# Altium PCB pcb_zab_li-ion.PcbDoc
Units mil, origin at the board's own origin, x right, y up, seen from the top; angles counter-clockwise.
Board outline 1000 x 550 mil, 2 copper layers (Top Layer, Bottom Layer); 14 components, 7 nets, 29 pads, 0 vias.
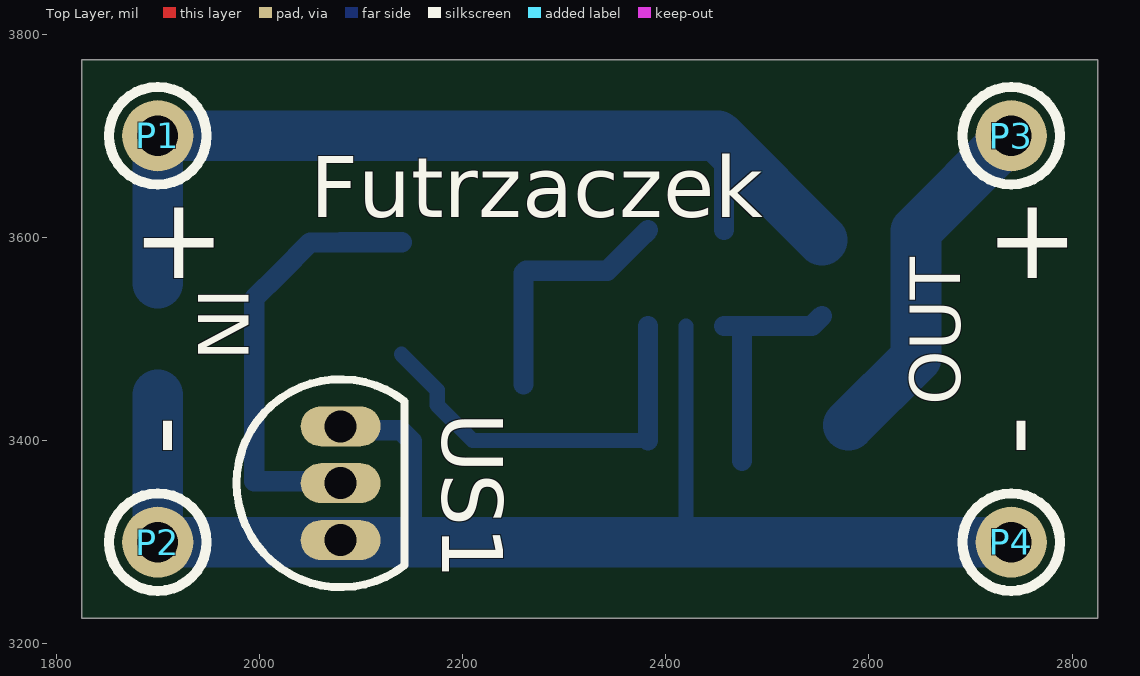
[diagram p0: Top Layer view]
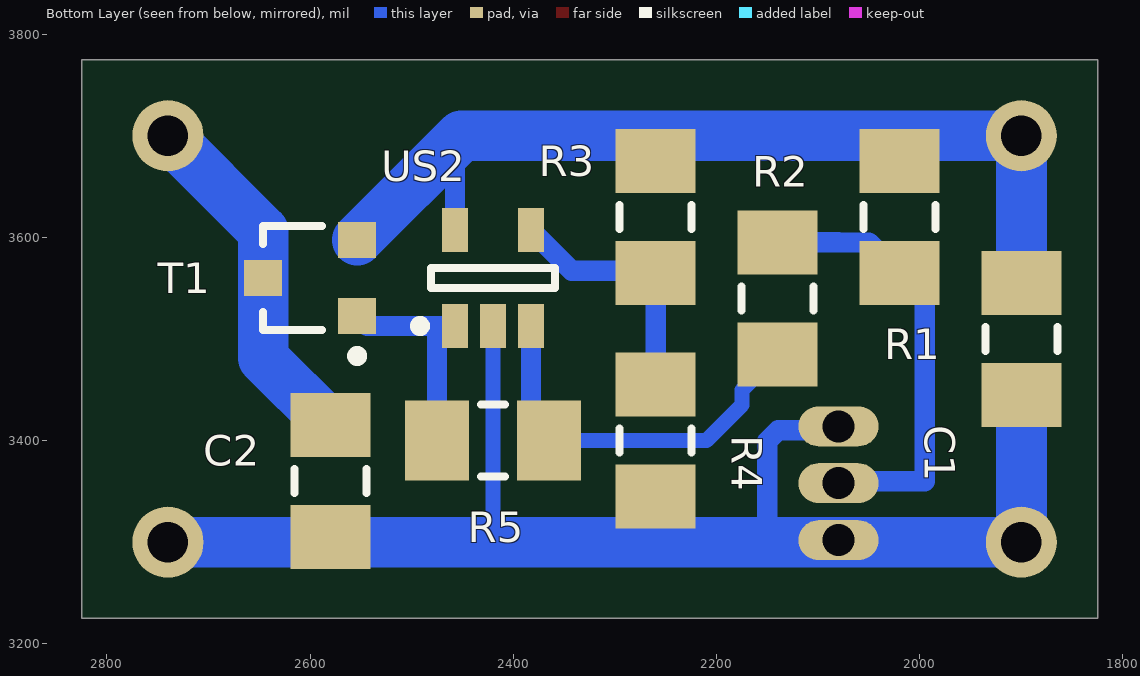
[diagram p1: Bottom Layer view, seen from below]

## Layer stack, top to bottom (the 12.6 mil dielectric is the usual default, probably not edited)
Top Layer: signal copper 1.4
Dielectric: dielectric 12.6, FR-4, Dk 4.8
Bottom Layer: signal copper 1.4

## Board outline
1825,3225 1825,3775 2825,3775 2825,3225

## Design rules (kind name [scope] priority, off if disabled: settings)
Clearance [All] p1: gap=10
PolygonConnect [All] p1: connectstyle=Relief reliefconductorwidth=10 reliefentries=4 polygonreliefangle="90 Angle"
RoutingVias [All] p1: holewidth=28 width=50 viastyle="Through Hole" minholewidth=28 minwidth=50 maxholewidth=28 maxwidth=50
SilkscreenOverComponentPads [All] p1: minsilkscreentomaskgap=10
SolderMaskExpansion [All] p1: expansion=4
Width [All] p1: maxlimit=100 minlimit=10 preferedwidth=20
27 further rules are at their usual default settings.

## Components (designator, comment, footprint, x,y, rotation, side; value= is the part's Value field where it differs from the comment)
C1 "100n" MELF-1206 1900,3500 r90 bottom
C2 "100n" MELF-1206 2580,3360 r90 bottom
P1 "Pad" "pad fi 1mm" 1900,3700 r0 top
P2 "Pad" "pad fi 1mm" 1900,3300 r0 top
P3 "Pad" "pad fi 1mm" 2740,3700 r0 top
P4 "Pad" "pad fi 1mm" 2740,3300 r0 top
R1 "82k" MELF-1206 2020,3620 r90 bottom
R2 "3,3k" MELF-1206 2140,3540 r90 bottom
R3 "750k" MELF-1206 2260,3620 r90 bottom
R4 "470k" MELF-1206 2260,3400 r270 bottom
R5 "82k" MELF-1206 2420,3400 r0 bottom
T1 "IRLML6402" SOT-23 2600,3560 r90 bottom
US1 "LM385BZ-1.2" 29-04 2080,3358 r0 top
US2 "MCP6001T-E/OT" SOT-23-OT5_N 2420,3560 r90 bottom

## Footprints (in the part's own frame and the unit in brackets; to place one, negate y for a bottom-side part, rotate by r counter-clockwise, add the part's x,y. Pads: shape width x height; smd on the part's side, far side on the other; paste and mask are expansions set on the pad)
29-04 [mm] "TO, Flat Index; 3 In-Line, Axial Leads; Body Dia. 4.8mm; Leads 0.48 x 0.5 mm (max)"
  oval 2x1 hole 0.8: 1(0,-1.422) 2(0,0) 3(0,1.422)
  silkscreen extent -2.6,-2.6 1.6,2.6
MELF-1206 [mm] "Metal Electrode Face (MELF) Resistor; Body 3.2 x 1.8 mm (LxDia)"
  rect 1.6x2 smd: 1(-1.4,0) 2(1.4,0)
  silkscreen extent -0.3,-0.9 0.3,0.9, body extent -2.3,-1.1 2.3,1.1, height 1.85
"pad fi 1mm" [mil]
  round 70 hole 40: 1(0,0)
  silkscreen extent -48,-48 48,48
SOT-23 [mm] "SOT-23; 3 Leads; Body 3.1 x 2.5 mm, inc. leads (LxW max)"
  rect 0.9x0.95 smd: 1(-0.95,-1.175) 2(0.95,-1.175) 3(0,1.175)
  silkscreen extent -2.07,-1.3 1.3,1.18
SOT-23-OT5_N [mm] "SOT23, 5-Leads, Body 2.9x1.6mm, Pitch 0.95mm, Lead Span 2.7mm, IPC Medium Density"
  rect 1.1x0.65 smd: 1(-1.2,0.95) 2(-1.2,0) 3(-1.2,-0.95) 4(1.2,-0.95) 5(1.2,0.95)
  silkscreen extent -1.32,-1.55 0.25,1.95, body extent -0.9,-1.55 0.9,1.55, height 1.45

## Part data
C1 C2: library part kondensator
R1 R2 R3 R4 R5: library part rezystor
T1: library part IRLML6302, "HEXFET Power MOSFET"
US1: "Micropower Voltage Reference Diode"
US2: "1 MHz, Low-Power Operational Amplifier, 5-Pin SOT-23, Extended Temperature, Tape and Reel"

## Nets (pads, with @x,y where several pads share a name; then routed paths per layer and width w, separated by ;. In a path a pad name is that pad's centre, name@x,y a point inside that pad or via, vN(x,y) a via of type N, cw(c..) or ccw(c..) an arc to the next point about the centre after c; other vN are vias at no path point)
NetC1_1: C1.1 C2.1 P2.1 P4.1 R4.2 US1.1 US1.3 US2.2 | length 1405.6
  Bottom Layer w15: 2420,3300 US2.2
  Bottom Layer w20: US1.1@2070,3300 US1.1@2080,3310 ; US1.3@2080,3410 2139.37,3410 2150,3399.37 2150,3371.44 2150,3300
  Bottom Layer w50: C1.1 P2.1 2025,3300 ; 2015,3300 2070,3300 2080,3300 2150,3300 ; 2140,3300 2420,3300 P4.1
NetC1_2: C1.2 P1.1 R1.2 R3.2 T1.2 US2.5 | length 909
  Bottom Layer w20: US2.5 2457.4,3675.12
  Bottom Layer w50: C1.2 P1.1 2260,3700 2451.14,3700 T1.2
NetC2_2: C2.2 P3.1 T1.3 | length 351.2
  Bottom Layer w50: C2.2 2646.26,3481.38 T1.3 2646.26,3606.26 P3.1
NetR1_1: R1.1 R2.2 US1.2 | length 432.8
  Bottom Layer w20: US1.2@2080,3360 1995,3360 1995,3539.88 R1.1 2050.12,3595 2080,3595 2080.12,3595.12 R2.2
NetR2_1: R2.1 R5.1 US2.3 | length 399.2
  Bottom Layer w15: R2.1 2175,3449.88 2175,3435 2210,3400 R5.1@2382.6,3400
  Bottom Layer w20: R5.1@2382.6,3400 US2.3
NetR3_1: R3.1 R4.1 US2.4 | length 249.9
  Bottom Layer w20: R4.1 R3.1 2262.36,3567.24 2342.6,3567.24 2372.6,3597.24 US2.4
NetR5_2: R5.2 T1.1 US2.1 | length 233.2
  Bottom Layer w20: US2.1 2543.9,3512.76 T1.1 ; R5.2@2475.12,3380 2475.12,3512.76

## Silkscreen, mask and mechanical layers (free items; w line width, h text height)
Top Overlay:
  text "Futrzaczek" at 2050,3620 h60
  text "+" at 1875,3560 h80
  text "+" at 2715,3560 h80
  text "IN" at 1940,3550 h50 r270
  text "OUT" at 2690,3435 h50 r90
  text "-" at 1940,3385 h80 r90
  text "-" at 2780,3385 h80 r90
Mechanical 1:
  the board outline again, w10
